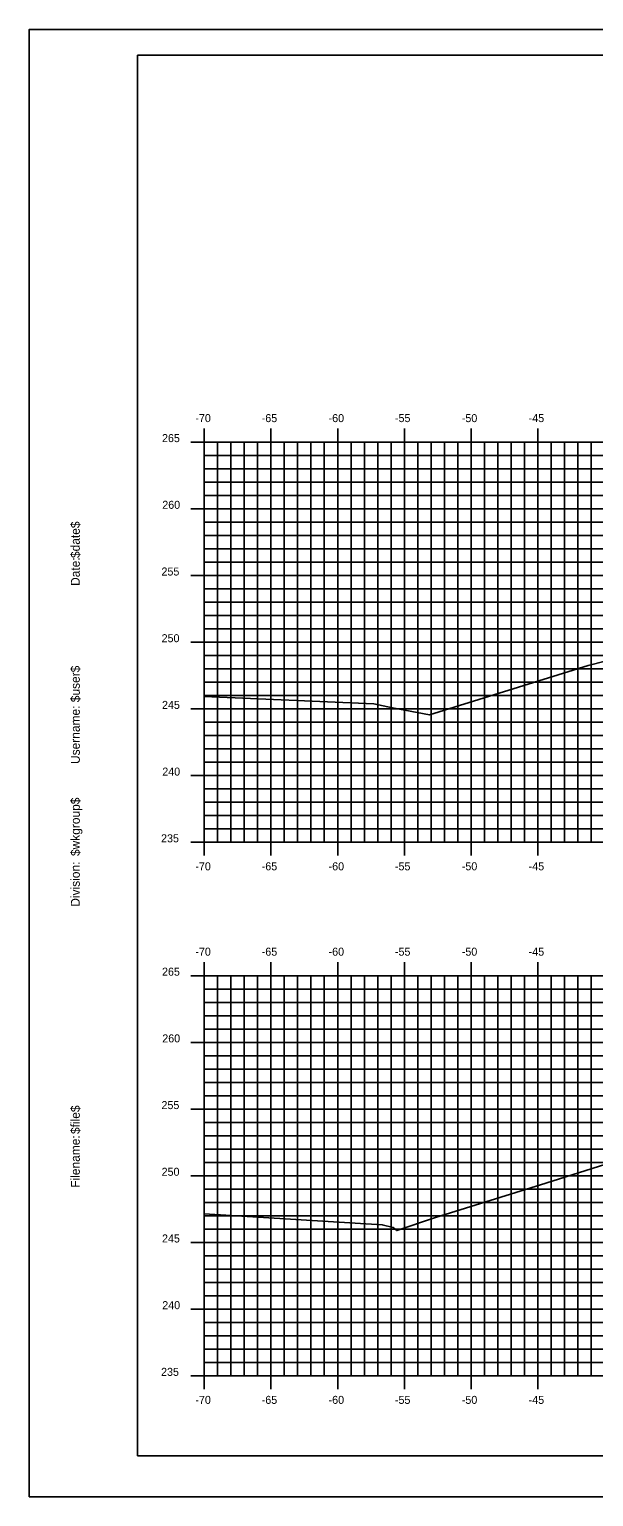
# Model space of a CAD drawing. Extents: x -22 to 1480, y -1511 to 8.
# Drawn here: x 199.6 to 241.9, y -184.5 to -74.5 of the extents above; entities that cross this region are included whole.
import ezdxf

# ---------------------------------------------------------------- set-up
doc = ezdxf.new("R2010")
doc.units = 0
for name, color, linetype in [('BORDER', 7, 'Continuous'), ('H_V ANNOTATION', 7, 'Continuous'), ('MAJOR', 7, 'Continuous'), ('MINOR', 7, 'Continuous'), ('PLOT BOUNDARY', 7, 'Continuous'), ('S_Roadway_Centerline', 7, 'Continuous')]:
    doc.layers.add(name, color=color, linetype=linetype)

msp = doc.modelspace()

# ---------------------------------------------------------------- linework, layer by layer
at = {"layer": 'BORDER'}
for p, q in [((367.7, -76.47), (207.7, -76.47)), ((207.7, -76.47), (207.7, -181.47)), ((207.7, -181.47), (367.7, -181.47))]:
    msp.add_line(p, q, dxfattribs=at)
at = {"layer": 'MAJOR'}
for p, q in [((212.7, -104.46), (212.7, -105.47)), ((217.7, -104.46), (217.7, -105.47)), ((222.7, -104.46), (222.7, -105.47)), ((227.7, -104.46), (227.7, -105.47)), ((232.7, -104.46), (232.7, -105.47)), ((237.7, -104.46), (237.7, -105.47)), ((211.69, -105.47), (212.7, -105.47)), ((212.7, -105.47), (352.7, -105.47)), ((212.7, -135.47), (212.7, -105.47)), ((212.7, -135.47), (212.7, -105.47)), ((212.7, -105.47), (352.7, -105.47)), ((217.7, -135.47), (217.7, -105.47)), ((222.7, -135.47), (222.7, -105.47)), ((227.7, -135.47), (227.7, -105.47)), ((232.7, -135.47), (232.7, -105.47)), ((237.7, -135.47), (237.7, -105.47)), ((211.69, -110.47), (212.7, -110.47)), ((212.7, -110.47), (352.7, -110.47)), ((211.69, -115.47), (212.7, -115.47)), ((212.7, -115.47), (352.7, -115.47)), ((211.69, -120.47), (212.7, -120.47)), ((212.7, -120.47), (352.7, -120.47)), ((211.69, -125.47), (212.7, -125.47)), ((212.7, -125.47), (352.7, -125.47)), ((211.69, -130.47), (212.7, -130.47)), ((212.7, -130.47), (352.7, -130.47)), ((211.69, -135.47), (212.7, -135.47)), ((212.7, -135.47), (352.7, -135.47)), ((212.7, -135.47), (352.7, -135.47)), ((212.7, -136.47), (212.7, -135.47)), ((217.7, -136.47), (217.7, -135.47)), ((222.7, -136.47), (222.7, -135.47)), ((227.7, -136.47), (227.7, -135.47)), ((232.7, -136.47), (232.7, -135.47)), ((237.7, -136.47), (237.7, -135.47)), ((212.7, -144.46), (212.7, -145.47)), ((217.7, -144.46), (217.7, -145.47)), ((222.7, -144.46), (222.7, -145.47)), ((227.7, -144.46), (227.7, -145.47)), ((232.7, -144.46), (232.7, -145.47)), ((237.7, -144.46), (237.7, -145.47)), ((211.69, -145.47), (212.7, -145.47)), ((212.7, -145.47), (352.7, -145.47)), ((212.7, -175.47), (212.7, -145.47)), ((212.7, -175.47), (212.7, -145.47)), ((212.7, -145.47), (352.7, -145.47)), ((217.7, -175.47), (217.7, -145.47)), ((222.7, -175.47), (222.7, -145.47)), ((227.7, -175.47), (227.7, -145.47)), ((232.7, -175.47), (232.7, -145.47)), ((237.7, -175.47), (237.7, -145.47)), ((211.69, -150.47), (212.7, -150.47)), ((212.7, -150.47), (352.7, -150.47)), ((211.69, -155.47), (212.7, -155.47)), ((212.7, -155.47), (352.7, -155.47)), ((211.69, -160.47), (212.7, -160.47)), ((212.7, -160.47), (352.7, -160.47)), ((211.69, -165.47), (212.7, -165.47)), ((212.7, -165.47), (352.7, -165.47)), ((211.69, -170.47), (212.7, -170.47)), ((212.7, -170.47), (352.7, -170.47)), ((211.69, -175.47), (212.7, -175.47)), ((212.7, -175.47), (352.7, -175.47)), ((212.7, -175.47), (352.7, -175.47)), ((212.7, -176.47), (212.7, -175.47)), ((217.7, -176.47), (217.7, -175.47)), ((222.7, -176.47), (222.7, -175.47)), ((227.7, -176.47), (227.7, -175.47)), ((232.7, -176.47), (232.7, -175.47)), ((237.7, -176.47), (237.7, -175.47))]:
    msp.add_line(p, q, dxfattribs=at)
at = {"layer": 'MINOR'}
for p, q in [((213.7, -135.47), (213.7, -105.47)), ((214.7, -135.47), (214.7, -105.47)), ((215.7, -135.47), (215.7, -105.47)), ((216.7, -135.47), (216.7, -105.47)), ((218.7, -135.47), (218.7, -105.47)), ((219.7, -135.47), (219.7, -105.47)), ((220.7, -135.47), (220.7, -105.47)), ((221.7, -135.47), (221.7, -105.47)), ((223.7, -135.47), (223.7, -105.47)), ((224.7, -135.47), (224.7, -105.47)), ((225.7, -135.47), (225.7, -105.47)), ((226.7, -135.47), (226.7, -105.47)), ((228.7, -135.47), (228.7, -105.47)), ((229.7, -135.47), (229.7, -105.47)), ((230.7, -135.47), (230.7, -105.47)), ((231.7, -135.47), (231.7, -105.47)), ((233.7, -135.47), (233.7, -105.47)), ((234.7, -135.47), (234.7, -105.47)), ((235.7, -135.47), (235.7, -105.47)), ((236.7, -135.47), (236.7, -105.47)), ((238.7, -135.47), (238.7, -105.47)), ((239.7, -135.47), (239.7, -105.47)), ((240.7, -135.47), (240.7, -105.47)), ((241.7, -135.47), (241.7, -105.47)), ((212.7, -106.47), (352.7, -106.47)), ((212.7, -106.47), (213.7, -106.47)), ((212.7, -107.47), (352.7, -107.47)), ((212.7, -107.47), (213.7, -107.47)), ((212.7, -108.47), (352.7, -108.47)), ((212.7, -108.47), (213.7, -108.47)), ((212.7, -109.47), (352.7, -109.47)), ((212.7, -109.47), (213.7, -109.47)), ((212.7, -111.47), (352.7, -111.47)), ((212.7, -111.47), (213.7, -111.47)), ((212.7, -112.47), (352.7, -112.47)), ((212.7, -112.47), (213.7, -112.47)), ((212.7, -113.47), (352.7, -113.47)), ((212.7, -113.47), (213.7, -113.47)), ((212.7, -114.47), (352.7, -114.47)), ((212.7, -114.47), (213.7, -114.47)), ((212.7, -116.47), (352.7, -116.47)), ((212.7, -116.47), (213.7, -116.47)), ((212.7, -117.47), (352.7, -117.47)), ((212.7, -117.47), (213.7, -117.47)), ((212.7, -118.47), (352.7, -118.47)), ((212.7, -118.47), (213.7, -118.47)), ((212.7, -119.47), (352.7, -119.47)), ((212.7, -119.47), (213.7, -119.47)), ((212.7, -121.47), (352.7, -121.47)), ((212.7, -121.47), (213.7, -121.47)), ((212.7, -122.47), (352.7, -122.47)), ((212.7, -122.47), (213.7, -122.47)), ((212.7, -123.47), (352.7, -123.47)), ((212.7, -123.47), (213.7, -123.47)), ((212.7, -124.47), (352.7, -124.47)), ((212.7, -124.47), (213.7, -124.47)), ((212.7, -126.47), (352.7, -126.47)), ((212.7, -126.47), (213.7, -126.47)), ((212.7, -127.47), (352.7, -127.47)), ((212.7, -127.47), (213.7, -127.47)), ((212.7, -128.47), (352.7, -128.47)), ((212.7, -128.47), (213.7, -128.47)), ((212.7, -129.47), (352.7, -129.47)), ((212.7, -129.47), (213.7, -129.47)), ((212.7, -131.47), (352.7, -131.47)), ((212.7, -131.47), (213.7, -131.47)), ((212.7, -132.47), (352.7, -132.47)), ((212.7, -132.47), (213.7, -132.47)), ((212.7, -133.47), (352.7, -133.47)), ((212.7, -133.47), (213.7, -133.47)), ((212.7, -134.47), (352.7, -134.47)), ((212.7, -134.47), (213.7, -134.47)), ((213.7, -175.47), (213.7, -145.47)), ((214.7, -175.47), (214.7, -145.47)), ((215.7, -175.47), (215.7, -145.47)), ((216.7, -175.47), (216.7, -145.47)), ((218.7, -175.47), (218.7, -145.47)), ((219.7, -175.47), (219.7, -145.47)), ((220.7, -175.47), (220.7, -145.47)), ((221.7, -175.47), (221.7, -145.47)), ((223.7, -175.47), (223.7, -145.47)), ((224.7, -175.47), (224.7, -145.47)), ((225.7, -175.47), (225.7, -145.47)), ((226.7, -175.47), (226.7, -145.47)), ((228.7, -175.47), (228.7, -145.47)), ((229.7, -175.47), (229.7, -145.47)), ((230.7, -175.47), (230.7, -145.47)), ((231.7, -175.47), (231.7, -145.47)), ((233.7, -175.47), (233.7, -145.47)), ((234.7, -175.47), (234.7, -145.47)), ((235.7, -175.47), (235.7, -145.47)), ((236.7, -175.47), (236.7, -145.47)), ((238.7, -175.47), (238.7, -145.47)), ((239.7, -175.47), (239.7, -145.47)), ((240.7, -175.47), (240.7, -145.47)), ((241.7, -175.47), (241.7, -145.47)), ((212.7, -146.47), (352.7, -146.47)), ((212.7, -146.47), (213.7, -146.47)), ((212.7, -147.47), (352.7, -147.47)), ((212.7, -147.47), (213.7, -147.47)), ((212.7, -148.47), (352.7, -148.47)), ((212.7, -148.47), (213.7, -148.47)), ((212.7, -149.47), (352.7, -149.47)), ((212.7, -149.47), (213.7, -149.47)), ((212.7, -151.47), (352.7, -151.47)), ((212.7, -151.47), (213.7, -151.47)), ((212.7, -152.47), (352.7, -152.47)), ((212.7, -152.47), (213.7, -152.47)), ((212.7, -153.47), (352.7, -153.47)), ((212.7, -153.47), (213.7, -153.47)), ((212.7, -154.47), (352.7, -154.47)), ((212.7, -154.47), (213.7, -154.47)), ((212.7, -156.47), (352.7, -156.47)), ((212.7, -156.47), (213.7, -156.47)), ((212.7, -157.47), (352.7, -157.47)), ((212.7, -157.47), (213.7, -157.47)), ((212.7, -158.47), (352.7, -158.47)), ((212.7, -158.47), (213.7, -158.47)), ((212.7, -159.47), (352.7, -159.47)), ((212.7, -159.47), (213.7, -159.47)), ((212.7, -161.47), (352.7, -161.47)), ((212.7, -161.47), (213.7, -161.47)), ((212.7, -162.47), (352.7, -162.47)), ((212.7, -162.47), (213.7, -162.47)), ((212.7, -163.47), (352.7, -163.47)), ((212.7, -163.47), (213.7, -163.47)), ((212.7, -164.47), (352.7, -164.47)), ((212.7, -164.47), (213.7, -164.47)), ((212.7, -166.47), (352.7, -166.47)), ((212.7, -166.47), (213.7, -166.47)), ((212.7, -167.47), (352.7, -167.47)), ((212.7, -167.47), (213.7, -167.47)), ((212.7, -168.47), (352.7, -168.47)), ((212.7, -168.47), (213.7, -168.47)), ((212.7, -169.47), (352.7, -169.47)), ((212.7, -169.47), (213.7, -169.47)), ((212.7, -171.47), (352.7, -171.47)), ((212.7, -171.47), (213.7, -171.47)), ((212.7, -172.47), (352.7, -172.47)), ((212.7, -172.47), (213.7, -172.47)), ((212.7, -173.47), (352.7, -173.47)), ((212.7, -173.47), (213.7, -173.47)), ((212.7, -174.47), (352.7, -174.47)), ((212.7, -174.47), (213.7, -174.47))]:
    msp.add_line(p, q, dxfattribs=at)
at = {"layer": 'PLOT BOUNDARY'}
msp.add_lwpolyline([(199.6, -184.53), (369.6, -184.53), (369.6, -74.53), (199.6, -74.53)], close=True, dxfattribs=at)
at = {"layer": 'S_Roadway_Centerline'}
for points in [[(212.7, -124.54), (225.41, -125.09), (226.82, -125.38), (229.57, -125.91), (241.47, -122.21), (254.51, -118.9)], [(212.7, -163.33), (226.04, -164.14), (226.86, -164.35), (227.13, -164.58), (230.03, -163.61), (238.3, -161.03), (256.61, -155.22)]]:
    msp.add_lwpolyline(points, dxfattribs=at)

# ---------------------------------------------------------------- texts
at = {"layer": 'BORDER'}
for s, p in [('$date$', (203.38, -114.16)), ('Date:', (203.38, -116.25)), ('$user$', (203.38, -124.97)), ('Username:', (203.38, -129.6)), ('$wkgroup$', (203.38, -136.5)), ('Division:', (203.38, -140.3)), ('$file$', (203.38, -157.34)), ('Filename:', (203.38, -161.37))]:
    msp.add_text(s, height=0.67, rotation=90, dxfattribs=at).set_placement(p)
at = {"layer": 'H_V ANNOTATION'}
for s, p in [('-70', (212.04, -103.97)), ('-65', (217.01, -103.97)), ('-60', (222.02, -103.97)), ('-55', (226.99, -103.97)), ('-50', (232, -103.97)), ('-45', (237.01, -103.97)), ('265', (209.54, -105.47)), ('260', (209.56, -110.47)), ('255', (209.5, -115.47)), ('250', (209.51, -120.47)), ('245', (209.54, -125.47)), ('240', (209.56, -130.47)), ('235', (209.47, -135.47)), ('-70', (212.04, -137.57)), ('-65', (217.01, -137.57)), ('-60', (222.02, -137.57)), ('-55', (226.99, -137.57)), ('-50', (232, -137.57)), ('-45', (237.01, -137.57)), ('-70', (212.04, -143.97)), ('-65', (217.01, -143.97)), ('-60', (222.02, -143.97)), ('-55', (226.99, -143.97)), ('-50', (232, -143.97)), ('-45', (237.01, -143.97)), ('265', (209.54, -145.47)), ('260', (209.56, -150.47)), ('255', (209.5, -155.47)), ('250', (209.51, -160.47)), ('245', (209.54, -165.47)), ('240', (209.56, -170.47)), ('235', (209.47, -175.47)), ('-70', (212.04, -177.57)), ('-65', (217.01, -177.57)), ('-60', (222.02, -177.57)), ('-55', (226.99, -177.57)), ('-50', (232, -177.57)), ('-45', (237.01, -177.57))]:
    msp.add_text(s, height=0.6, dxfattribs=at).set_placement(p)

doc.saveas('drawing.dxf')
